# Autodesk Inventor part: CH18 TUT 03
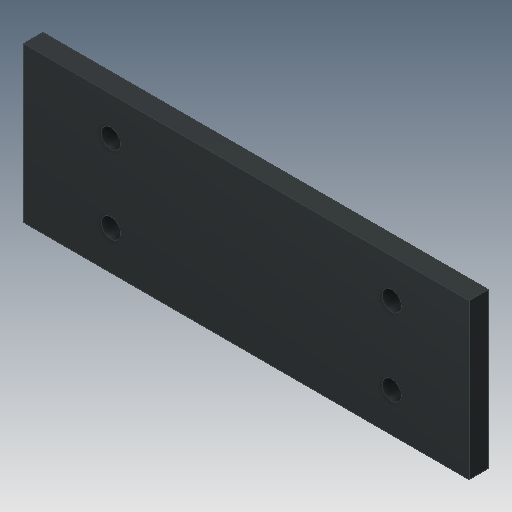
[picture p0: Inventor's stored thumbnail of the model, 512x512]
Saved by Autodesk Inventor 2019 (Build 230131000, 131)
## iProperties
Created: 2016-05
Part Number: CH18 TUT 03
Material: Iron, Cast
Document SubType Name: Modeling
Designer: CADCIM
Density: 7.15 g/cm^3
Appearance: Iron Gray
Mass: 161.642 g
Surface Area: 109.071 cm^2
Volume: 22.6073 cm^3
Author: CADCIM
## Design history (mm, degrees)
sketch "Sketch1"
  geometry: L1 (0, 40)-(115, 40); L2 (115, 40)-(115, 0); L3 (115, 0)-(0, 0); L4 (0, 0)-(0, 40); C1 r 2.5 at (22.5, 30); C2 r 2.5 at (95, 30); C3 r 2.5 at (22.5, 10); C4 r 2.5 at (95, 10); 1 further point
  constraints: 8 end point, 4 centre point, 2 horizontal, 2 parallel, 1 coincident, 1 perpendicular, 1 vertical, 6 other
  dimensions: "d0" = 115 distance of L1.start L1.end; "d1" = 40 distance of L1.end L2.end; "d2" = 10 distance from line of L1 C1.centre; "d3" = 22.5 distance from line of L4 C1.centre; "d6" = 72.5 distance of C1.centre C2.centre; "d9" = 20 distance of C1.centre C3.centre; "d14" = 5 diameter of C2
extrude "Extrusion1" new body sketch "Sketch1" distance "d12" = 5; taper "d13" = 0 deg
body "Solid1"
